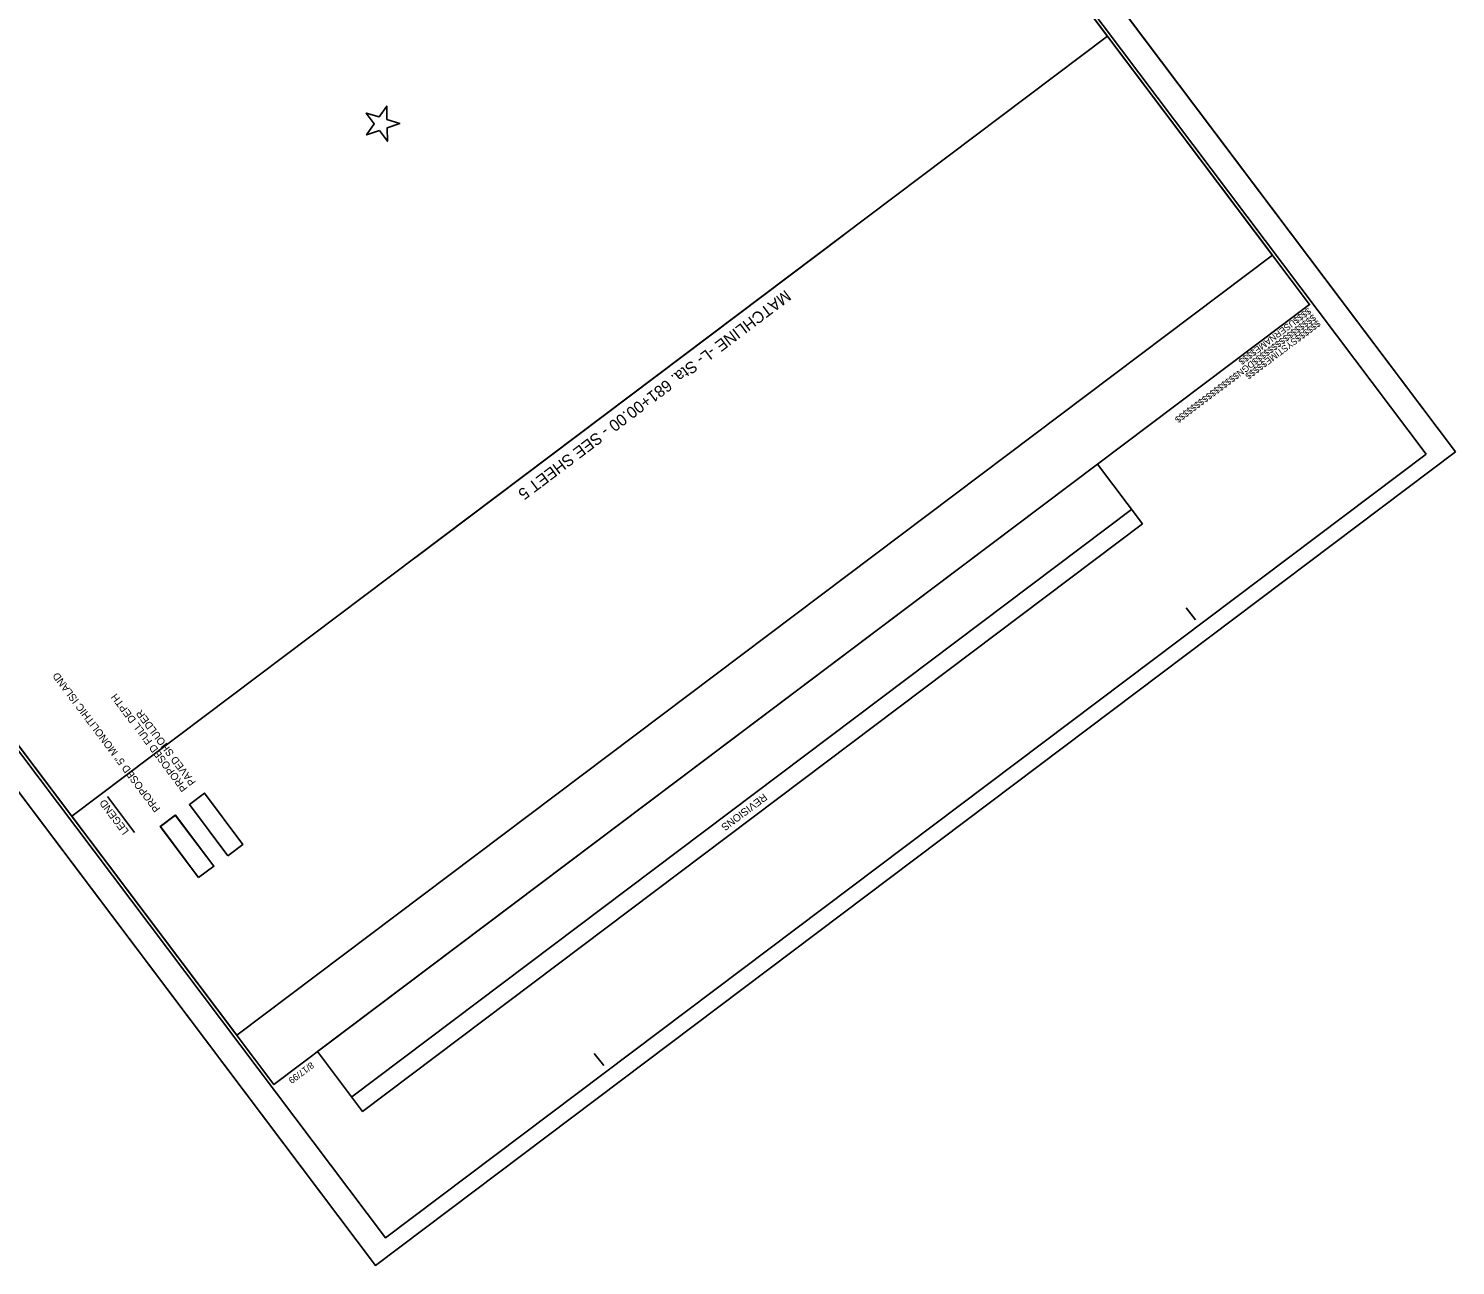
# Model space of a CAD drawing. Extents: x 1261689 to 1263694, y 776294 to 778298.
# Drawn here: x 1262538 to 1263694, y 776294 to 777296 of the extents above; entities that cross this region are included whole.
import ezdxf

# ---------------------------------------------------------------- set-up
doc = ezdxf.new("R2010")
doc.units = 0
for name, color, linetype in [('Matchline', 7, 'Continuous'), ('Old_Level_1', 7, 'Continuous'), ('Prop RDY Traffic Signal CELL', 7, 'Continuous'), ('Prop Shade Light', 7, 'Continuous'), ('Prop Shade Medium', 7, 'Continuous'), ('Sheet Block Revision CELL', 7, 'Continuous'), ('Sheet Clip Boundary CELL', 7, 'Continuous'), ('Sheet Cutting Line CELL', 7, 'Continuous'), ('Sheet Layout Plan Border', 7, 'Continuous'), ('Sheet Plan CELL', 7, 'Continuous'), ('Sheet Plan Layout CELL', 7, 'Continuous'), ('Sheet Plot Border Inside CELL', 7, 'Continuous'), ('Sheet Plot Border Outside CELL', 7, 'Continuous')]:
    doc.layers.add(name, color=color, linetype=linetype)

msp = doc.modelspace()

# ---------------------------------------------------------------- linework, layer by layer
at = {"layer": 'Matchline'}
msp.add_line((1263198.2, 777128.4), (1262851.6, 776867.3), dxfattribs=at)
at = {"layer": 'Prop RDY Traffic Signal CELL'}
msp.add_lwpolyline([(1262822.4, 777213.2), (1262828.9, 777204.5), (1262828.7, 777215.3), (1262839, 777218.9), (1262828.6, 777222.1), (1262828.4, 777233), (1262822.2, 777224.1), (1262811.8, 777227.2), (1262818.3, 777218.5), (1262812.1, 777209.6), (1262822.4, 777213.2)], dxfattribs=at)
at = {"layer": 'Prop Shade Light'}
msp.add_lwpolyline([(1262699.8, 776625.8), (1262712, 776635), (1262680.9, 776676.4), (1262668.7, 776667.2)], close=True, dxfattribs=at)
at = {"layer": 'Prop Shade Medium'}
msp.add_lwpolyline([(1262676.1, 776608.1), (1262688.4, 776617.3), (1262657.3, 776658.7), (1262645.1, 776649.5)], close=True, dxfattribs=at)
at = {"layer": 'Sheet Block Revision CELL'}
msp.add_line((1263431.6, 776906.1), (1262800.1, 776430.5), dxfattribs=at)
msp.add_lwpolyline([(1263440.4, 776894.5), (1262808.8, 776418.8), (1262772.4, 776467.2), (1263403.9, 776942.9)], close=True, dxfattribs=at)
at = {"layer": 'Sheet Clip Boundary CELL'}
msp.add_lwpolyline([(1263412, 777289.5), (1262673.2, 778270.4), (1262003.4, 777765.9), (1262147.4, 777574.8), (1261978.4, 777447.5), (1262573.3, 776657.8)], close=True, dxfattribs=at)
at = {"layer": 'Sheet Cutting Line CELL'}
for p, q in [((1263693.8, 776952.8), (1262681, 778297.5)), ((1261806.3, 777638.7), (1262819.2, 776294)), ((1262819.2, 776294), (1263693.8, 776952.8))]:
    msp.add_line(p, q, dxfattribs=at)
at = {"layer": 'Sheet Layout Plan Border'}
msp.add_lwpolyline([(1263545.6, 777112.2), (1262703.3, 778230.4), (1262033.5, 777726), (1262147.4, 777574.8), (1261978.4, 777447.5), (1262706.9, 776480.4)], close=True, dxfattribs=at)
at = {"layer": 'Sheet Plan CELL'}
for p, q in [((1263575.7, 777072.2), (1263575.7, 777072.2)), ((1263483.3, 776816.8), (1263475.8, 776826.7)), ((1262624.2, 776644.7), (1262602.4, 776673.7)), ((1263004.1, 776455.8), (1262996.5, 776465.7)), ((1262737, 776440.5), (1262737, 776440.5))]:
    msp.add_line(p, q, dxfattribs=at)
for points in [[(1261834.5, 777638.7), (1262737, 776440.5), (1263575.7, 777072.2), (1262673.2, 778270.4)], [(1262699.8, 776625.8), (1262712, 776635), (1262680.8, 776676.5), (1262668.6, 776667.3)], [(1262676.1, 776608.1), (1262688.4, 776617.3), (1262657.2, 776658.8), (1262645, 776649.6)]]:
    msp.add_lwpolyline(points, close=True, dxfattribs=at)
at = {"layer": 'Sheet Plan Layout CELL'}
msp.add_lwpolyline([(1262737, 776440.5), (1263575.7, 777072.2), (1262673.2, 778270.4), (1262003.4, 777765.9), (1262147.4, 777574.8), (1261978.4, 777447.5)], close=True, dxfattribs=at)
at = {"layer": 'Sheet Plot Border Inside CELL'}
msp.add_lwpolyline([(1263670, 776951.1), (1262667.7, 778281.9), (1261825, 777647.1), (1262827.3, 776316.4)], close=True, dxfattribs=at)
at = {"layer": 'Sheet Plot Border Outside CELL'}
msp.add_lwpolyline([(1263693.8, 776952.8), (1262681, 778297.5), (1261806.3, 777638.7), (1262819.2, 776294)], close=True, dxfattribs=at)

# ---------------------------------------------------------------- texts
at = {"layer": 'Matchline'}
msp.add_text('MATCHLINE -L- Sta. 681+00.00 - SEE SHEET 5', height=9.375, rotation=216.9874, dxfattribs=at).set_placement((1263151.2, 777084.5))
at = {"layer": 'Old_Level_1'}
for s, p in [('PROPOSED 5" MONOLITHIC ISLAND', (1262645.4, 776663.9)), ('PROPOSED FULL DEPTH', (1262667.5, 776680.4)), ('PAVED SHOULDER', (1262674.1, 776685.4)), ('LEGEND', (1262619.9, 776645.7))]:
    msp.add_text(s, height=6, rotation=126.8862, dxfattribs=at).set_placement(p)
at = {"layer": 'Sheet Block Revision CELL'}
msp.add_text('REVISIONS', height=6, rotation=216.9874, dxfattribs=at).set_placement((1263133.6, 776676.6))
at = {"layer": 'Sheet Plan CELL'}
for s, p in [('$$$$$$$$$$$$$$$$DGN$$$$$$$$$$$$$$$$', (1263578.4, 777064.7)), ('$$$$USERNAME$$$$', (1263574.4, 777069.9)), ('$$$$$$SYSTIME$$$$$', (1263582.1, 777059.9)), ('8/17/99', (1262767, 776459.1))]:
    msp.add_text(s, height=5.25, rotation=216.9874, dxfattribs=at).set_placement(p)

doc.saveas('drawing.dxf')
